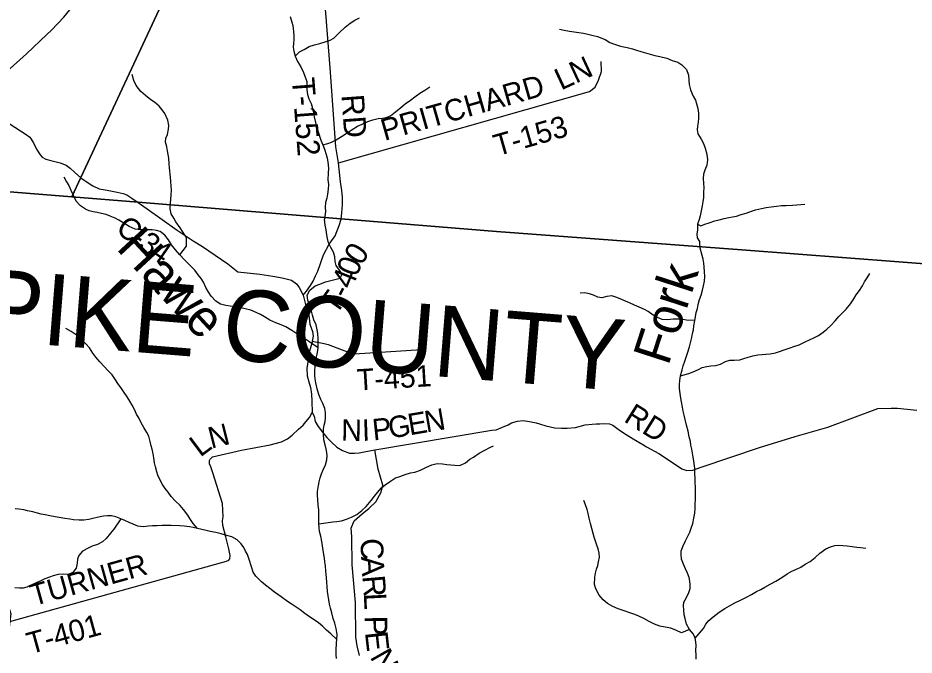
# Model space of a CAD drawing. Extents: x -139 to 835, y 0 to 440.
# Drawn here: x 167 to 242.7, y 290.4 to 344.1 of the extents above; entities that cross this region are included whole.
import ezdxf

# ---------------------------------------------------------------- set-up
doc = ezdxf.new("R2010")
doc.units = 0
for name, color, linetype in [('GM_X_County_Road', 7, 'Continuous'), ('GM_X_County_Road_Text', 7, 'Continuous'), ('GM_X_County_Text', 7, 'Continuous'), ('GM_X_Minor_River', 7, 'Continuous'), ('GM_X_Minor_River_Text', 7, 'Continuous'), ('GM_X_State_Route', 7, 'Continuous'), ('GM_X_Township_Road', 7, 'Continuous'), ('GM_X_Township_Road_Text', 7, 'Continuous'), ('SH_Cut_Line', 7, 'Continuous')]:
    doc.layers.add(name, color=color, linetype=linetype)

msp = doc.modelspace()

# ---------------------------------------------------------------- linework, layer by layer
at = {"layer": 'GM_X_County_Road'}
for points in [[(163.548, 336.843), (166.278, 335.235), (167.722, 334.302), (168.024, 334.061), (168.341, 333.594), (168.595, 333.052), (168.897, 332.571), (169.07, 332.384), (169.358, 332.21), (169.788, 332.102), (170.593, 331.911), (171.089, 331.705), (171.414, 331.456), (171.801, 331.133), (172.329, 330.652), (172.606, 330.457), (172.693, 330.399)], [(172.693, 330.399), (173.333, 329.972), (173.875, 329.723), (174.556, 329.591), (175.408, 329.429), (175.903, 329.326), (176.198, 329.203), (176.644, 328.929), (177.162, 328.559)], [(177.162, 328.559), (177.93, 328.027), (180.463, 326.216), (181.818, 325.328), (182.595, 324.837), (184.731, 323.369), (185.581, 322.697), (187.442, 322.521), (188.543, 322.34), (189.34, 322.211), (190.111, 322.01), (190.525, 321.692), (190.775, 321.375), (191.11, 320.733), (191.304, 319.935), (191.572, 319.051), (191.665, 318.279), (191.874, 317.673), (191.933, 317.287), (191.865, 316.852), (191.851, 316.757), (191.639, 316), (191.53, 315.289), (191.407, 314.543), (191.438, 313.915), (191.585, 313.431), (191.731, 312.935), (191.801, 312.38), (191.845, 311.776), (191.872, 310.823), (192.021, 310.508), (192.117, 310.061), (192.378, 309.636), (192.728, 309.162), (193.103, 308.711), (193.478, 308.321), (193.943, 307.918), (194.434, 307.612), (195.014, 307.412), (195.42, 307.396), (195.841, 307.423), (196.242, 307.503), (197.159, 307.679), (207.043, 309.334), (207.391, 309.381), (207.926, 309.596), (208.397, 309.788), (208.69, 309.956), (209.199, 310.111), (209.683, 310.158), (210.204, 310.06), (210.776, 309.95), (211.042, 309.877), (211.576, 309.706), (211.945, 309.633), (212.351, 309.523), (212.898, 309.498), (213.381, 309.496), (214.093, 309.579), (214.921, 309.781), (215.506, 309.84), (215.836, 309.875), (216.154, 309.874), (216.536, 309.909), (216.956, 309.884), (217.235, 309.763), (217.59, 309.52), (217.882, 309.29), (218.377, 308.987), (218.973, 308.612), (219.773, 308.127), (220.078, 307.921), (221.118, 307.364), (222.108, 306.722), (223.073, 306.08), (223.492, 305.946), (223.988, 305.968), (224.701, 306.22), (229.627, 307.87), (232.644, 308.802), (235.394, 309.59), (239.63, 311.16), (240.757, 311.192), (241.269, 311.192), (242.908, 311.03)], [(195.846, 290.323), (195.653, 291.121), (195.56, 291.858), (195.53, 294.79), (195.237, 297.978), (195.2, 300.342), (195.158, 301.078), (195.405, 301.679), (196.084, 302.275), (196.672, 302.763), (197.236, 303.3), (197.689, 304.115), (197.822, 304.693), (197.432, 306.036), (197.159, 307.679)]]:
    msp.add_lwpolyline(points, dxfattribs=at)
at = {"layer": 'GM_X_County_Text'}
for points in [[(205.139, 401.486), (87.298, 401.486), (90.116, 391.109), (100.145, 354.177), (105.67, 333.828), (158.444, 330.1), (160.688, 329.921), (171.559, 329.033), (172.321, 330.669), (184.767, 357.384), (185.383, 358.364), (185.729, 359.048), (185.902, 359.821), (186.018, 360.334), (186.292, 360.95), (186.616, 361.275), (187.014, 361.689), (203.078, 396.689), (203.294, 397.153), (203.246, 397.371), (203.278, 397.973), (203.623, 399.152)], [(295.458, 319.381), (295.458, 401.486), (205.139, 401.486), (203.623, 399.152), (203.278, 397.973), (203.246, 397.371), (203.294, 397.153), (203.078, 396.689), (187.014, 361.689), (186.616, 361.275), (186.292, 360.95), (186.018, 360.334), (185.902, 359.821), (185.729, 359.048), (185.383, 358.364), (184.767, 357.384), (172.321, 330.669), (171.559, 329.033), (177.155, 328.576), (194.287, 327.176), (207.436, 326.102), (228.151, 324.569), (267.909, 321.538)]]:
    msp.add_lwpolyline(points, close=True, dxfattribs=at)
msp.add_lwpolyline([(267.909, 321.538), (228.151, 324.569), (207.436, 326.102), (194.287, 327.176), (177.155, 328.576), (171.559, 329.033), (160.688, 329.921), (158.512, 319.627), (166.41, 293.836), (166.338, 293.196), (164.238, 274.594)], dxfattribs=at)
at = {"layer": 'GM_X_Minor_River'}
for points in [[(190.007, 344.266), (190.141, 343.794), (190.213, 343.492), (190.283, 343.009), (190.304, 342.623), (190.3, 342.322), (190.271, 341.984), (190.267, 341.659), (190.314, 341.345), (190.422, 340.91), (190.607, 340.474), (190.893, 340.001), (191.128, 339.54), (191.25, 339.225), (191.397, 338.765), (191.405, 338.367), (191.414, 338.066), (191.472, 337.668), (191.582, 337.305), (191.767, 336.905), (191.876, 336.53), (191.96, 336.143), (192.032, 335.781), (192.14, 335.31), (192.237, 334.959), (192.358, 334.512), (192.591, 333.822), (192.763, 333.422), (192.898, 333.071), (193.032, 332.624), (193.117, 332.297), (193.176, 331.995), (193.246, 331.452), (193.215, 331.043), (193.195, 330.464), (193.229, 330.066), (193.224, 329.68), (193.168, 329.271), (193.088, 328.935), (192.982, 328.562), (192.964, 328.177), (192.998, 327.803)], [(190.422, 340.91), (190.782, 341.28), (191.177, 341.48), (191.611, 341.728), (192.044, 341.88), (192.514, 341.995), (192.946, 342.135), (193.366, 342.275), (193.698, 342.428), (194.147, 342.869), (194.647, 343.37), (195.056, 343.691), (195.465, 343.963), (195.848, 344.152)], [(212.731, 343.183), (213.15, 343.094), (213.581, 343.018), (213.974, 342.953), (214.38, 342.901), (214.761, 342.849), (215.142, 342.773), (215.471, 342.698), (215.953, 342.56), (216.585, 342.313), (217.002, 342.068), (217.382, 341.932), (217.901, 341.758), (218.459, 341.632), (218.903, 341.531), (219.232, 341.407), (219.612, 341.307), (220.005, 341.207), (220.385, 341.094), (220.803, 340.982), (221.209, 340.893), (221.804, 340.731), (222.26, 340.558), (222.728, 340.396), (223.069, 340.188), (223.458, 339.775), (223.631, 339.303), (223.677, 338.893), (223.698, 338.507), (223.807, 338.06), (224.043, 337.54), (224.217, 337.189), (224.352, 336.802), (224.425, 336.488), (224.471, 336.102), (224.479, 335.68), (224.463, 335.343), (224.408, 334.994), (224.353, 334.681), (224.426, 334.355), (224.713, 333.894), (224.912, 333.531), (225.047, 333.144), (225.181, 332.637), (225.24, 332.166), (225.171, 331.721), (225.013, 331.301), (224.895, 330.941), (224.865, 330.591), (224.899, 330.193), (224.92, 329.784), (224.903, 329.458), (224.898, 328.977), (224.843, 328.604), (224.788, 328.279), (224.707, 327.87), (224.613, 327.437), (224.533, 327.113), (224.402, 326.728), (224.396, 326.246), (224.341, 325.898), (224.363, 325.572), (224.563, 325.257), (224.569, 325.007), (224.599, 324.823)], [(179.867, 328.106), (179.963, 329.215), (179.981, 329.588), (179.96, 329.926), (179.939, 330.336), (179.893, 330.698), (179.827, 331.494), (179.793, 331.82), (179.748, 332.291), (179.701, 332.605), (179.654, 332.931), (179.582, 333.245), (179.486, 333.656), (179.49, 333.993), (179.646, 334.305), (179.715, 334.738), (179.757, 335.051), (179.686, 335.522), (179.427, 336.067), (179.203, 336.383), (178.928, 336.7), (178.552, 337.017), (178.225, 337.226), (177.786, 337.592), (177.384, 337.934), (176.998, 338.433), (176.813, 338.845), (176.654, 339.353)], [(192.763, 333.422), (193.17, 333.538), (193.501, 333.643), (193.896, 333.843), (194.343, 334.14), (194.726, 334.377), (195.161, 334.673), (195.684, 334.993), (196.079, 335.181), (196.551, 335.405), (196.971, 335.545), (197.441, 335.648), (197.796, 335.668), (198.113, 335.725), (198.47, 335.877), (198.905, 336.21), (199.341, 336.591), (199.712, 336.888), (200.159, 337.208), (200.53, 337.482), (200.939, 337.79), (201.361, 338.039), (201.795, 338.311)], [(170.884, 330.715), (171.107, 330.302), (171.305, 329.987), (171.491, 329.587), (171.895, 328.689)], [(192.367, 316.29), (191.592, 316.834), (191.147, 317.112), (190.804, 317.354), (190.486, 317.535), (190.143, 317.764), (189.635, 318.054), (189.254, 318.223), (188.783, 318.393), (188.288, 318.622), (187.843, 318.912), (187.5, 319.105), (187.144, 319.287), (186.687, 319.468), (186.216, 319.589), (185.848, 319.661), (185.403, 319.746), (184.946, 319.794), (184.577, 319.855), (184.119, 319.975), (183.726, 320.229), (183.344, 320.64), (183.065, 321.051), (182.887, 321.389), (182.684, 321.824), (182.494, 322.138), (182.24, 322.464), (181.96, 322.85), (181.503, 323.309), (181.071, 323.72), (180.677, 324.143), (180.334, 324.554), (179.991, 324.976), (179.724, 325.399), (179.419, 325.798), (179.038, 326.1), (178.708, 326.208), (178.352, 326.257), (178.034, 326.257), (177.691, 326.245), (177.373, 326.245), (176.928, 326.305), (176.395, 326.547), (175.963, 326.813), (175.543, 327.054), (175.213, 327.235), (174.806, 327.417), (174.476, 327.538), (174.082, 327.634), (173.713, 327.707), (173.37, 327.767), (173.027, 327.864), (172.709, 327.997), (172.303, 328.275), (171.895, 328.689)], [(224.402, 326.728), (224.68, 326.581), (225.012, 326.722), (225.382, 326.851), (225.854, 327.003), (226.224, 327.108), (226.657, 327.212), (227.027, 327.293), (227.358, 327.362), (227.689, 327.419), (228.072, 327.535), (228.505, 327.652), (228.952, 327.816), (229.297, 327.945), (229.806, 328.06), (230.189, 328.141), (230.622, 328.197), (231.067, 328.253), (231.487, 328.297), (231.894, 328.317), (232.403, 328.336), (232.772, 328.356), (233.128, 328.377), (233.446, 328.41)], [(180.677, 324.143), (181.237, 324.867), (181.237, 325.616), (180.97, 326.039), (180.716, 326.426), (180.361, 326.933), (180.183, 327.235), (179.967, 327.609), (179.878, 328.02), (179.867, 328.106)], [(192.998, 327.803), (192.912, 327.153)], [(191.593, 319.987), (191.492, 320.301), (191.428, 320.735), (191.657, 321.17), (192.115, 321.532), (192.509, 321.677), (192.98, 321.858), (193.335, 321.955), (193.768, 322.064), (194.213, 322.172), (194.403, 322.498), (194.175, 322.849), (193.883, 323.247), (193.794, 323.586), (193.781, 323.96), (193.654, 324.371), (193.426, 324.757), (193.248, 325.144), (193.159, 325.53), (193.109, 325.832), (193.045, 326.243), (192.956, 326.641), (192.912, 327.153)], [(224.205, 304.919), (224.19, 305.245), (224.173, 305.715), (224.156, 306.125), (224.127, 306.535), (224.06, 306.92), (223.993, 307.221), (223.912, 307.727), (223.845, 308.076), (223.792, 308.377), (223.699, 308.775), (223.593, 309.256), (223.461, 309.773), (223.355, 310.231), (223.275, 310.616), (223.195, 310.941), (223.116, 311.278), (223.035, 311.736), (222.981, 312.049), (222.927, 312.446), (222.885, 312.868), (222.882, 313.206), (222.891, 313.543), (222.964, 313.93), (223.099, 314.438), (223.198, 314.764), (223.334, 315.176), (223.446, 315.502), (223.557, 315.841), (223.718, 316.385), (223.828, 316.82), (223.914, 317.171), (223.974, 317.509), (224.048, 317.811), (224.083, 318.149), (224.168, 318.584), (224.229, 318.898), (224.289, 319.273), (224.387, 319.624), (224.461, 319.938), (224.571, 320.373), (224.695, 320.748), (224.806, 321.147), (224.891, 321.534), (224.977, 321.932), (225.012, 322.307), (224.995, 322.716), (224.966, 323.138), (224.937, 323.452), (224.871, 323.765), (224.791, 324.077), (224.599, 324.823)], [(222.964, 313.93), (223.675, 314.117), (224.017, 314.253), (224.473, 314.474), (224.803, 314.622), (225.196, 314.722), (225.514, 314.773), (225.934, 314.813), (226.327, 314.901), (226.771, 315.123), (227.113, 315.246), (227.495, 315.238), (227.966, 315.29), (228.321, 315.378), (228.676, 315.502), (229.07, 315.614), (229.476, 315.69), (229.845, 315.73), (230.163, 315.745), (230.519, 315.784), (230.976, 315.86), (231.332, 315.984), (231.725, 316.109), (232.207, 316.294), (232.537, 316.417), (232.968, 316.554), (233.488, 316.788), (233.855, 316.972), (234.223, 317.144), (234.615, 317.341), (234.994, 317.622), (235.323, 317.866), (235.651, 318.171), (236.017, 318.56), (236.331, 318.937), (236.634, 319.241), (236.936, 319.557), (237.327, 320.007), (237.59, 320.431), (237.803, 320.759), (238.08, 321.123), (238.318, 321.524), (238.506, 321.851), (238.732, 322.203), (238.957, 322.567)], [(224.168, 318.584), (223.468, 318.626), (223.149, 318.672), (222.805, 318.705), (222.347, 318.712), (221.838, 318.648), (221.418, 318.68), (221.009, 318.857), (220.638, 319.059), (220.241, 319.344), (219.921, 319.522), (219.461, 319.735), (219.078, 319.889), (218.643, 320.102), (218.324, 320.244), (217.864, 320.432), (217.506, 320.574), (217.175, 320.667), (216.742, 320.627), (216.323, 320.515), (215.992, 320.572), (215.608, 320.749), (215.289, 320.855), (214.843, 320.923), (214.5, 320.908)], [(193.904, 290.064), (193.878, 290.379), (193.879, 290.777), (193.917, 291.345), (193.955, 291.659), (193.968, 292.094), (193.88, 292.589), (193.765, 293.061), (193.626, 293.447), (193.512, 293.906), (193.41, 294.305), (193.334, 294.655), (193.271, 295.006), (193.207, 295.368), (193.157, 295.731), (193.119, 296.141), (193.094, 296.48), (193.056, 296.915), (193.018, 297.434), (192.98, 297.881), (192.942, 298.231), (192.891, 298.545), (192.828, 299.017), (192.689, 299.947), (192.587, 300.394), (192.486, 300.78), (192.448, 301.119), (192.435, 301.433), (192.436, 302.218), (192.411, 302.605), (192.373, 303.003), (192.335, 303.474), (192.309, 303.813), (192.322, 304.175), (192.399, 304.658), (192.463, 304.972), (192.539, 305.31), (192.654, 305.649), (192.781, 305.987), (192.972, 306.422), (193.099, 306.832), (193.137, 307.195), (193.074, 307.63), (192.96, 308.089), (192.846, 308.524), (192.808, 309.007), (192.808, 309.417), (192.885, 309.756), (192.948, 310.07), (192.987, 310.384), (192.987, 310.819), (192.923, 311.157), (192.758, 311.58), (192.593, 311.918), (192.416, 312.341), (192.289, 312.824), (192.175, 313.331), (192.124, 313.681), (192.086, 313.995), (192.073, 314.346), (192.099, 314.732), (192.163, 315.119), (192.239, 315.517), (192.316, 315.892), (192.367, 316.29), (192.367, 317.051), (192.329, 317.51), (192.291, 317.824), (192.19, 318.235), (192.012, 318.658), (191.898, 319.056), (191.771, 319.491), (191.593, 319.987)], [(182.178, 301.048), (181.809, 301.458), (181.543, 301.869), (181.365, 302.171), (181.009, 302.63), (180.704, 302.968), (180.298, 303.379), (179.968, 303.754), (179.688, 304.116), (179.46, 304.418), (179.218, 304.744), (179.028, 305.131), (178.837, 305.53), (178.749, 305.832), (178.622, 306.254), (178.558, 306.593), (178.495, 306.991), (178.444, 307.354), (178.355, 307.728), (178.279, 308.03), (178.191, 308.38), (178.064, 308.827), (177.899, 309.129), (177.657, 309.564), (177.429, 309.963), (177.251, 310.325), (177.035, 310.688), (176.845, 311.074), (176.654, 311.449), (176.476, 311.775), (176.235, 312.149), (175.994, 312.524), (175.765, 312.862), (175.46, 313.285), (175.257, 313.587), (174.965, 313.998), (174.609, 314.372), (174.317, 314.698), (173.923, 315.109), (173.58, 315.496), (173.339, 315.846), (173.047, 316.281), (172.755, 316.619), (172.386, 317.006), (171.929, 317.392), (171.497, 317.682), (171.065, 317.936)], [(192.435, 301.433), (193.592, 301.59), (193.935, 301.638), (194.329, 301.698), (194.762, 301.831), (195.181, 302), (195.626, 302.218), (196.046, 302.556), (196.427, 302.894), (196.847, 303.389), (197.114, 303.776), (197.381, 304.09), (197.712, 304.476), (198.03, 304.73), (198.462, 305.032), (198.894, 305.31), (199.263, 305.442), (199.721, 305.599), (200.153, 305.732), (200.534, 305.805), (201.017, 305.974), (201.513, 306.203), (201.958, 306.421), (202.403, 306.529), (202.873, 306.493), (203.242, 306.445), (203.56, 306.42), (203.903, 306.384), (204.335, 306.348), (204.805, 306.577), (205.174, 306.879), (205.492, 307.06), (205.95, 307.398), (206.433, 307.664), (206.852, 307.882), (207.17, 308.026)], [(224.292, 290.011), (224.276, 290.36), (224.26, 290.734), (224.269, 291.169), (224.253, 291.47), (224.2, 291.771), (224.044, 292.107), (223.709, 292.503), (223.476, 292.959), (223.344, 293.428), (223.278, 293.753), (223.236, 294.175), (223.22, 294.513), (223.243, 294.814), (223.455, 295.226), (223.668, 295.626), (223.766, 295.977), (223.789, 296.279), (223.761, 296.58), (223.682, 296.893), (223.564, 297.254), (223.395, 297.626), (223.213, 298.023), (223.056, 298.456), (223.002, 298.841), (223.011, 299.167), (223.173, 299.578), (223.373, 300.003), (223.561, 300.342), (223.761, 300.73), (223.872, 301.056), (223.996, 301.468), (224.093, 301.915), (224.166, 302.326), (224.188, 302.736), (224.197, 303.134), (224.219, 303.472), (224.229, 303.774), (224.237, 304.22), (224.222, 304.534), (224.205, 304.919)], [(193.955, 291.659), (193.434, 292.155), (193.066, 292.469), (192.736, 292.807), (192.393, 293.073), (192.024, 293.327), (191.63, 293.593), (191.249, 293.87), (190.855, 294.16), (190.436, 294.45), (190.093, 294.668), (189.775, 294.873), (189.229, 295.26), (188.683, 295.659), (188.276, 295.961), (187.908, 296.263), (187.577, 296.541), (187.095, 297.012), (186.879, 297.362), (186.726, 297.797), (186.549, 298.426), (186.396, 298.836), (186.244, 299.138), (186.079, 299.44), (185.863, 299.742), (185.52, 300.081), (185.063, 300.334), (184.656, 300.443), (184.186, 300.576), (183.728, 300.697), (183.258, 300.794), (182.902, 300.878), (182.546, 300.951), (182.178, 301.048), (181.822, 301.12), (181.504, 301.168), (181.059, 301.241), (180.665, 301.265), (179.954, 301.289), (179.204, 301.29), (178.771, 301.265), (178.365, 301.253), (178.034, 301.229), (177.602, 301.193), (177.132, 301.241), (176.738, 301.399), (176.42, 301.556), (176.039, 301.713), (175.709, 301.858), (175.277, 302.015), (174.908, 302.099), (174.565, 302.099), (174.247, 302.075), (173.828, 302.003), (173.344, 301.894), (172.989, 301.798), (172.569, 301.737), (172.188, 301.737), (171.718, 301.762), (171.387, 301.822), (170.98, 301.895), (170.485, 301.979), (170.167, 302.015), (169.697, 302.1), (169.303, 302.185), (168.985, 302.257), (168.655, 302.342), (168.286, 302.438), (167.829, 302.535), (167.511, 302.608), (167.104, 302.668), (166.786, 302.704)], [(223.709, 292.503), (223.037, 292.243), (222.615, 292.432), (222.143, 292.621), (221.671, 292.713), (221.212, 292.805), (220.765, 292.958), (220.318, 293.195), (219.87, 293.445), (219.448, 293.634), (219.116, 293.775), (218.771, 293.905), (218.107, 294.116), (217.699, 294.257), (217.239, 294.446), (216.791, 294.695), (216.432, 295.03), (216.098, 295.413), (215.8, 295.953), (215.708, 296.302), (215.727, 296.929), (215.788, 297.267), (215.874, 297.606), (215.973, 297.908), (216.046, 298.223), (216.119, 298.621), (216.09, 298.947), (215.998, 299.32), (215.893, 299.645), (215.775, 299.981), (215.671, 300.294), (215.591, 300.619), (215.486, 301.04), (215.354, 301.449), (215.236, 301.907), (215.156, 302.292), (215.089, 302.629), (214.945, 303.038), (214.789, 303.41)], [(175.709, 301.858), (175.111, 300.988), (174.831, 300.65), (174.462, 300.203), (174.144, 299.901), (173.725, 299.696), (173.28, 299.539), (172.936, 299.382), (172.479, 299.128), (172.148, 298.766), (172.046, 298.439), (172.008, 298.113), (171.931, 297.69), (171.639, 297.328), (171.257, 297.147), (170.851, 297.171), (170.419, 297.159), (169.999, 297.038), (169.669, 296.93), (169.3, 296.797), (168.944, 296.628), (168.562, 296.459), (168.13, 296.265), (167.774, 296.096), (167.456, 296.012), (167.139, 296), (166.757, 296.024)], [(224.2, 291.771), (224.905, 292.598), (225.092, 292.961), (225.344, 293.265), (225.71, 293.582), (226.215, 293.985), (226.696, 294.291), (227.101, 294.524), (227.545, 294.769), (228.089, 295.027), (228.533, 295.236), (228.951, 295.47), (229.381, 295.715), (229.736, 295.899), (230.078, 296.083), (230.534, 296.328), (231.015, 296.598), (231.508, 296.904), (231.964, 297.198), (232.356, 297.431), (232.749, 297.615), (233.129, 297.788), (233.496, 298.032), (233.901, 298.253), (234.343, 298.595), (234.734, 298.96), (235.227, 299.314), (235.62, 299.499), (235.988, 299.611), (236.319, 299.638), (236.676, 299.617), (237.045, 299.584), (237.453, 299.528), (237.848, 299.459), (238.166, 299.426), (238.599, 299.381)]]:
    msp.add_lwpolyline(points, dxfattribs=at)
at = {"layer": 'GM_X_State_Route'}
for points in [[(169.456, 342.731), (169.842, 343.097), (170.891, 344.193), (171.641, 345.121), (172.478, 346.266), (173.572, 347.645), (174.127, 348.498), (174.762, 349.526), (175.158, 350.028), (175.555, 350.438), (176.146, 350.906), (177.213, 351.692), (179.011, 353.013), (180.58, 354.075), (182.432, 355.2), (183.384, 355.898), (183.99, 356.486), (184.774, 357.368), (185.39, 358.347), (185.737, 359.031), (185.909, 359.804), (186.029, 360.462), (186.299, 360.934)], [(159.052, 330.859), (160.294, 332.461), (161.707, 334.257), (163.548, 336.843), (164.297, 337.814), (166.091, 339.625), (167.744, 341.108), (169.456, 342.731)]]:
    msp.add_lwpolyline(points, dxfattribs=at)
at = {"layer": 'GM_X_Township_Road'}
for points in [[(194.295, 327.159), (194.369, 327.701), (194.419, 328.371), (194.428, 328.995), (194.374, 329.583), (194.246, 330.318), (194.079, 331.912), (193.868, 333.247), (193.366, 339.941), (193.01, 344.553), (192.953, 345.122), (192.889, 345.511), (192.737, 345.914), (188.697, 353.173), (187.396, 355.966), (187.021, 356.883), (186.617, 358.306), (186.458, 359.442), (186.299, 360.934), (186.134, 362.165)], [(194.079, 331.912), (215.269, 337.942), (215.749, 338.293), (216.031, 338.9), (216.298, 339.61), (216.253, 340.458)], [(191.11, 320.733), (191.367, 321.08), (191.728, 321.558), (191.947, 321.93), (192.142, 322.362), (192.337, 322.77), (192.828, 324.147), (193.299, 325.05), (193.793, 325.743), (194.146, 326.613), (194.295, 327.159)], [(191.865, 316.852), (192.886, 316.668), (193.199, 316.571), (193.954, 316.289), (195.074, 315.879), (195.423, 315.782), (201.099, 316.162)], [(166.345, 293.179), (184.632, 298.284), (184.811, 298.378), (184.901, 298.486), (184.929, 298.751), (184.834, 299.331), (184.567, 300.335), (184.312, 301.278), (184.278, 301.677), (184.358, 302.026), (184.282, 303.16), (183.475, 305.726), (183.303, 306.234), (183.192, 306.489), (183.195, 306.766), (183.248, 306.899), (183.453, 307.101), (185.88, 307.654), (188.305, 308.111), (189.284, 308.342), (189.781, 308.614), (190.178, 308.923), (190.703, 309.412), (191.1, 309.758), (191.331, 310.033), (191.639, 310.415), (191.872, 310.823)]]:
    msp.add_lwpolyline(points, dxfattribs=at)
at = {"layer": 'SH_Cut_Line'}
for points in [[(295.458, 319.381), (295.458, 401.486), (67.578, 401.486), (67.578, 336.518), (92.493, 334.759), (105.67, 333.828), (158.444, 330.1), (160.688, 329.921), (171.559, 329.033), (177.155, 328.576), (194.287, 327.176), (207.436, 326.102), (228.151, 324.569), (267.909, 321.538)], [(67.578, 336.518), (67.578, 185.387), (295.458, 185.387), (295.458, 319.381), (267.909, 321.538), (228.151, 324.569), (207.436, 326.102), (194.287, 327.176), (177.155, 328.576), (171.559, 329.033), (160.688, 329.921), (158.444, 330.1), (105.67, 333.828), (92.493, 334.759)]]:
    msp.add_lwpolyline(points, close=True, dxfattribs=at)

# ---------------------------------------------------------------- texts
at = {"layer": 'GM_X_County_Road_Text'}
for s, height, rotation, p in [('C', 1.858, 324.13122, (175.175, 326.101)), ('-', 1.858, 324.16383, (176.42, 325.201)), ('3', 1.858, 324.35131, (177.047, 324.748)), ('4', 1.856, 325.36576, (178.013, 324.056)), ('N', 1.811, 9.70226, (201.498, 309.14)), ('RD', 1.8505, 327.96516, (218.087, 310.121)), ('N', 1.806, 358.79084, (194.298, 308.464)), ('I', 1.806, 2.00957, (196.096, 308.429)), ('P', 1.808, 6.0246, (197.03, 308.467)), ('G', 1.811, 9.59094, (198.442, 308.621)), ('E', 1.811, 9.699, (200.096, 308.9)), ('C', 1.904, 271.62995, (195.943, 300.195)), ('A', 1.904, 273.40499, (195.988, 298.655)), ('R', 1.904, 274.89756, (196.086, 297.02)), ('L', 1.904, 272.97462, (196.211, 295.557)), ('P', 1.904, 270.6163, (196.289, 293.671)), ('E', 1.904, 276.39845, (196.314, 292.264)), ('N', 1.895, 299.54706, (196.7, 290.196))]:
    msp.add_text(s, height=height, rotation=rotation, dxfattribs=at).set_placement(p)
at = {"layer": 'GM_X_County_Text'}
msp.add_text('PIKE COUNTY', height=6.02285, rotation=355.39853, dxfattribs=at).set_placement((163.594, 317.011))
at = {"layer": 'GM_X_Minor_River_Text'}
for s, height, rotation, p in [('Hawe', 3.131, 312.79895, (175.237, 324.669)), ('Fork', 3.1681, 72.03577, (221.92, 314.702))]:
    msp.add_text(s, height=height, rotation=rotation, dxfattribs=at).set_placement(p)
at = {"layer": 'GM_X_Township_Road_Text'}
for s, height, rotation, p in [('LN', 1.8358, 24.90453, (212.877, 338.004)), ('T-152', 1.9039, 274.43352, (190.139, 339.043)), ('PRITCHARD', 1.8192, 15.92508, (197.966, 333.756)), ('RD', 1.904, 274.15917, (194.321, 337.627)), ('T-153', 1.8192, 15.93198, (207.485, 332.458)), ('0', 1.891, 56.51196, (195.993, 323.162)), ('0', 1.9, 68.51005, (195.628, 322.207)), ('4', 1.9, 68.12604, (195.206, 321.155)), ('T', 1.889, 54.63446, (193.857, 318.967)), ('-', 1.897, 63.35423, (194.805, 320.341)), ('T-451', 1.8063, 3.45841, (195.683, 312.677)), ('N', 1.817, 14.27578, (183.339, 307.762)), ('L', 1.861, 36.92931, (182.406, 307.01)), ('TURNER', 1.8187, 15.61267, (168.34, 294.479)), ('T-401', 1.8184, 15.41781, (168.051, 290.417))]:
    msp.add_text(s, height=height, rotation=rotation, dxfattribs=at).set_placement(p)

doc.saveas('drawing.dxf')
